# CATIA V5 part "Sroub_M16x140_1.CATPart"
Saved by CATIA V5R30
Part number: Sroub_M16x140_1
Definition: E 1200_16x140_2
Nomenclature: E 1200_16x140_2
Source: Unknown
Description: PART--DESC
Bounding box of the stored display mesh (mm): x -152 to -128, y 125.01 to 148.99, z -24.3 to 131.7
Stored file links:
  E:\Bakalarka\Model\Forma_v7\Sroub_M16x140_1.CATPart
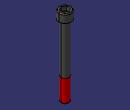
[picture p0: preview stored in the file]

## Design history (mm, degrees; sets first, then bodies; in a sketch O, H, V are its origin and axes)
Body1 "MANIFOLD_SOLID_BREP #3826" (main body)
  Solid1: solid without history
